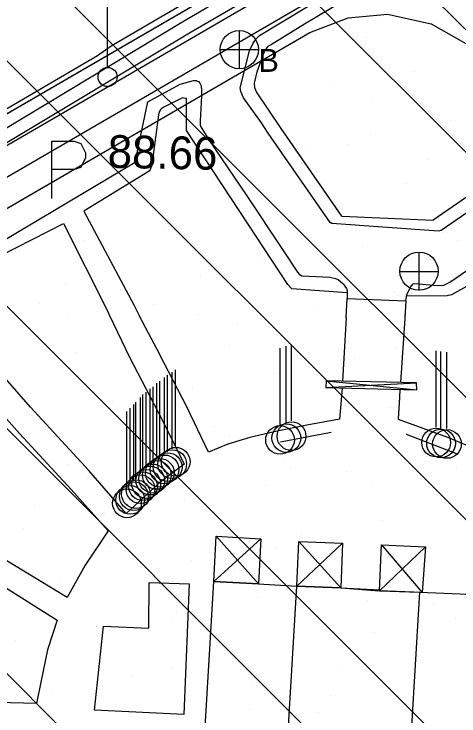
# Model space of a CAD drawing. Extents: x 417995 to 421451, y 4454518 to 4458015.
# Drawn here: x 420647.4 to 420728.9, y 4455736 to 4455864.6 of the extents above; entities that cross this region are included whole.
import ezdxf

# ---------------------------------------------------------------- set-up
doc = ezdxf.new("R2010")
doc.units = 0
for name, color, linetype in [('ADAKENARI', 7, 'Continuous'), ('B_Sundurma', 7, 'Continuous'), ('B_Teras', 7, 'Continuous'), ('B_Ticari', 7, 'Continuous'), ('KALDIRIM_FAT', 7, 'Continuous'), ('PL_AYA_FUAR', 7, 'Continuous'), ('PL_TA_K_OTOPARK', 7, 'Continuous'), ('S_Bayrak_Diregi', 7, 'Continuous'), ('S_Cad_Sok_Lambasi', 7, 'Continuous'), ('S_Otopark', 7, 'Continuous'), ('S_Rogar_Kapagi', 7, 'Continuous'), ('S_Rogar_Kapagi_Buski', 7, 'Continuous'), ('Sinir_Duvar_tek_tarafa_ait', 7, 'Continuous'), ('SN_TR_SIVILASMA', 7, 'Continuous'), ('TRFAT_PARKALANI', 7, 'Continuous'), ('Y_Kot_Noktasi', 7, 'Continuous'), ('Yol_Kaldirim_kenari_bordurtasi', 7, 'Continuous'), ('Yol_Sose', 7, 'Continuous')]:
    doc.layers.add(name, color=color, linetype=linetype)

msp = doc.modelspace()

# ---------------------------------------------------------------- linework, layer by layer
at = {"layer": 'ADAKENARI'}
for p, q in [((420604.42, 4455822.11), (420705.46, 4455880.83)), ((420701.58, 4455861.23), (420708.62, 4455863.92)), ((420708.62, 4455863.92), (420715.79, 4455864.57)), ((420715.79, 4455864.57), (420723.78, 4455862.78)), ((420723.78, 4455862.78), (420730.13, 4455859.19)), ((420636.29, 4455823.29), (420701.58, 4455861.23))]:
    msp.add_line(p, q, dxfattribs=at)
at = {"layer": 'B_Sundurma'}
for p, q in [((420704.5, 4455796.18), (420721.12, 4455797.04)), ((420704.55, 4455797.37), (420721.15, 4455795.75)), ((420684.45, 4455768.93), (420692.15, 4455760.19)), ((420684.01, 4455760.64), (420692.63, 4455768.41)), ((420699.18, 4455759.77), (420707.57, 4455767.63)), ((420707.23, 4455759.46), (420699.57, 4455767.97)), ((420714.33, 4455758.9), (420722.74, 4455766.97)), ((420714.69, 4455767.31), (420722.13, 4455758.62))]:
    msp.add_line(p, q, dxfattribs=at)
for points in [[(420704.55, 4455797.37), (420704.5, 4455796.18), (420721.15, 4455795.75), (420721.12, 4455797.04)], [(420684.01, 4455760.64), (420684.45, 4455768.93), (420692.63, 4455768.41), (420692.15, 4455760.19)], [(420707.23, 4455759.46), (420699.18, 4455759.77), (420699.57, 4455767.97), (420707.57, 4455767.63)], [(420714.33, 4455758.9), (420714.69, 4455767.31), (420722.74, 4455766.97), (420722.13, 4455758.62)]]:
    msp.add_lwpolyline(points, close=True, dxfattribs=at)
at = {"layer": 'B_Teras'}
msp.add_lwpolyline([(420707.23, 4455759.46), (420714.33, 4455759.07), (420714.33, 4455758.9), (420721.68, 4455758.64), (420713.06, 4455614.09), (420690.62, 4455615.29), (420699.18, 4455759.77)], close=True, dxfattribs=at)
at = {"layer": 'B_Ticari'}
msp.add_lwpolyline([(420697.3, 4455727.99), (420682.12, 4455728.78), (420684.01, 4455760.64), (420692.15, 4455760.19), (420699.18, 4455759.77), (420707.23, 4455759.46), (420714.33, 4455758.9), (420721.68, 4455758.64), (420729.13, 4455758.34), (420737.12, 4455757.88), (420735.52, 4455725.84), (420719.77, 4455726.58), (420713.06, 4455614.09), (420690.62, 4455615.29)], close=True, dxfattribs=at)
at = {"layer": 'KALDIRIM_FAT'}
for p, q in [((420608.38, 4455818.63), (420728.5, 4455888.44)), ((420612.88, 4455815.46), (420730.07, 4455883.57))]:
    msp.add_line(p, q, dxfattribs=at)
at = {"layer": 'PL_AYA_FUAR'}
msp.add_lwpolyline([(420545.42, 4455447.04), (420563.93, 4455742.84), (420564.49, 4455748.45), (420565.48, 4455754), (420566.88, 4455759.47), (420568.69, 4455764.8), (420570.9, 4455769.99), (420573.49, 4455775), (420576.46, 4455779.79), (420579.77, 4455784.35), (420583.42, 4455788.65), (420587.39, 4455792.66), (420591.64, 4455796.35), (420596.17, 4455799.72), (420600.93, 4455802.74), (420701.58, 4455861.23), (420708.62, 4455863.92), (420715.79, 4455864.57), (420723.78, 4455862.78), (420730.13, 4455859.19), (420735, 4455853.4), (420771.9, 4455797.51), (420787.06, 4455778.4), (420884.04, 4455668.02)], dxfattribs=at)
at = {"layer": 'PL_TA_K_OTOPARK'}
msp.add_lwpolyline([(420578.04, 4455894.75), (420621.81, 4455921.26), (420693.23, 4455965.73), (420713.63, 4455902.08), (420714.27, 4455899.43), (420714.5, 4455896.71), (420714.32, 4455893.98), (420713.73, 4455891.31), (420712.75, 4455888.76), (420711.4, 4455886.39), (420709.7, 4455884.25), (420707.71, 4455882.38), (420705.46, 4455880.83), (420604.42, 4455822.11), (420593.39, 4455815.7), (420591.4, 4455814.51), (420589.43, 4455813.26), (420587.5, 4455811.97), (420585.61, 4455810.62), (420583.75, 4455809.23), (420581.92, 4455807.78), (420580.13, 4455806.29), (420578.39, 4455804.76), (420550.56, 4455835.6)], close=True, dxfattribs=at)
at = {"layer": 'S_Bayrak_Diregi'}
for p, q in [((420696.12, 4455789.38), (420696.12, 4455803.38)), ((420697.26, 4455789.72), (420697.26, 4455803.72)), ((420698.23, 4455790.07), (420698.23, 4455804.07)), ((420724.69, 4455788.9), (420724.69, 4455802.9)), ((420725.59, 4455788.74), (420725.59, 4455802.74)), ((420726.68, 4455788.64), (420726.68, 4455802.64)), ((420675.53, 4455784.4), (420675.53, 4455798.4)), ((420676.37, 4455784.95), (420676.37, 4455798.95)), ((420677.01, 4455785.39), (420677.01, 4455799.39)), ((420673.56, 4455782.96), (420673.56, 4455796.96)), ((420674.09, 4455783.35), (420674.09, 4455797.35)), ((420674.97, 4455783.98), (420674.97, 4455797.98)), ((420672.36, 4455781.91), (420672.36, 4455795.91)), ((420672.88, 4455782.28), (420672.88, 4455796.28)), ((420671.02, 4455780.89), (420671.02, 4455794.89)), ((420671.62, 4455781.3), (420671.62, 4455795.3)), ((420669.33, 4455779.08), (420669.33, 4455793.08)), ((420669.72, 4455779.46), (420669.72, 4455793.46)), ((420670.56, 4455780.34), (420670.56, 4455794.34)), ((420668.66, 4455778.39), (420668.66, 4455792.39)), ((420668.08, 4455777.75), (420668.08, 4455791.75))]:
    msp.add_line(p, q, dxfattribs=at)
for centre in [(420697.27, 4455786.9), (420698.23, 4455787.25), (420696.12, 4455786.56), (420724.7, 4455786.08), (420725.6, 4455785.92), (420726.68, 4455785.82), (420675.54, 4455781.58), (420676.38, 4455782.13), (420677.02, 4455782.57), (420674.1, 4455780.53), (420674.97, 4455781.16), (420672.36, 4455779.1), (420672.88, 4455779.46), (420673.56, 4455780.14), (420671.03, 4455778.07), (420671.63, 4455778.48), (420669.73, 4455776.64), (420670.57, 4455777.52), (420668.67, 4455775.57), (420669.34, 4455776.26), (420668.09, 4455774.94)]:
    msp.add_circle(centre, 2.63, dxfattribs=at)
at = {"layer": 'S_Cad_Sok_Lambasi'}
msp.add_line((420664.55, 4455854.81), (420664.55, 4455869.48), dxfattribs=at)
msp.add_circle((420664.55, 4455853.06), 1.75, dxfattribs=at)
at = {"layer": 'S_Otopark'}
for points in [[(420654.33, 4455841.29), (420658.43, 4455841.29)], [(420654.33, 4455830.79), (420654.33, 4455841.29)], [(420658.43, 4455841.29), (420659.65, 4455840.87), (420660.49, 4455839.16), (420660.49, 4455838.25), (420659.65, 4455836.46), (420658.43, 4455836.11)], [(420658.43, 4455836.11), (420654.33, 4455836.11)]]:
    msp.add_lwpolyline(points, dxfattribs=at)
at = {"layer": 'S_Rogar_Kapagi'}
for p, q in [((420721.62, 4455813.95), (420721.62, 4455820.95)), ((420718.05, 4455817.41), (420725.05, 4455817.41))]:
    msp.add_line(p, q, dxfattribs=at)
msp.add_circle((420721.57, 4455817.48), 3.5, dxfattribs=at)
at = {"layer": 'S_Rogar_Kapagi_Buski'}
for p, q in [((420688.66, 4455861.57), (420688.66, 4455854.57)), ((420685.16, 4455858.07), (420692.16, 4455858.07))]:
    msp.add_line(p, q, dxfattribs=at)
msp.add_circle((420688.66, 4455858.07), 3.5, dxfattribs=at)
at = {"layer": 'Sinir_Duvar_tek_tarafa_ait'}
for points in [[(420696.19, 4455786.2), (420705.46, 4455788)], [(420719.19, 4455787.6), (420728.54, 4455784.04)]]:
    msp.add_lwpolyline(points, dxfattribs=at)
at = {"layer": 'SN_TR_SIVILASMA'}
for p, q in [((421269.77, 4455322.09), (420183.63, 4456408.23)), ((421269.54, 4455299.87), (420176.15, 4456393.26)), ((421269.08, 4455255.43), (420161.18, 4456363.33)), ((421268.85, 4455233.21), (420151.38, 4456350.68)), ((421268.38, 4455188.77), (420123.47, 4456333.68)), ((421268.15, 4455166.56), (420116.87, 4456317.84)), ((421267.69, 4455122.12), (420103.66, 4456286.14))]:
    msp.add_line(p, q, dxfattribs=at)
at = {"layer": 'TRFAT_PARKALANI'}
for p, q in [((420714.05, 4455863.09), (420714.05, 4455863.09)), ((420711.98, 4455860.33), (420711.98, 4455860.33)), ((420720.71, 4455854.11), (420720.71, 4455854.11)), ((420705.94, 4455851.51), (420705.94, 4455851.51)), ((420691.16, 4455848.9), (420691.16, 4455848.9)), ((420713.09, 4455849.38), (420713.09, 4455849.38)), ((420694.6, 4455848.16), (420694.6, 4455848.16)), ((420676.39, 4455846.3), (420676.39, 4455846.3)), ((420678.96, 4455845.84), (420678.96, 4455845.84)), ((420677.26, 4455845.42), (420677.26, 4455845.42)), ((420727.37, 4455845.13), (420727.37, 4455845.13)), ((420712.6, 4455842.53), (420712.6, 4455842.53)), ((420697.82, 4455839.92), (420697.82, 4455839.92)), ((420701.6, 4455839.74), (420701.6, 4455839.74)), ((420708.51, 4455840.63), (420708.51, 4455840.63)), ((420683.05, 4455837.32), (420683.05, 4455837.32)), ((420723.28, 4455838.03), (420723.28, 4455838.03)), ((420665.77, 4455835.78), (420665.77, 4455835.78)), ((420668.28, 4455834.71), (420668.28, 4455834.71)), ((420661.59, 4455833.68), (420661.59, 4455833.68)), ((420719.26, 4455833.55), (420719.26, 4455833.55)), ((420653.51, 4455832.11), (420653.51, 4455832.11)), ((420704.49, 4455830.94), (420704.49, 4455830.94)), ((420689.71, 4455828.34), (420689.71, 4455828.34)), ((420674.94, 4455825.73), (420674.94, 4455825.73)), ((420675.49, 4455826.15), (420675.49, 4455826.15)), ((420705.9, 4455825.86), (420705.9, 4455825.86)), ((420725.92, 4455824.57), (420725.92, 4455824.57)), ((420660.17, 4455823.13), (420660.17, 4455823.13)), ((420690.26, 4455823.54), (420690.26, 4455823.54)), ((420728.55, 4455823.18), (420728.55, 4455823.18)), ((420711.15, 4455821.96), (420711.15, 4455821.96)), ((420692.71, 4455819.22), (420692.71, 4455819.22)), ((420696.37, 4455819.36), (420696.37, 4455819.36)), ((420719.81, 4455818.33), (420719.81, 4455818.33)), ((420681.6, 4455816.75), (420681.6, 4455816.75)), ((420656.87, 4455815.26), (420656.87, 4455815.26)), ((420666.83, 4455814.15), (420666.83, 4455814.15)), ((420717.06, 4455813.54), (420717.06, 4455813.54)), ((420717.81, 4455812.98), (420717.81, 4455812.98)), ((420652.06, 4455811.54), (420652.06, 4455811.54)), ((420672.89, 4455811.38), (420672.89, 4455811.38)), ((420703.03, 4455810.38), (420703.03, 4455810.38)), ((420657.25, 4455809.06), (420657.25, 4455809.06)), ((420681.22, 4455809.58), (420681.22, 4455809.58)), ((420688.26, 4455807.77), (420688.26, 4455807.77)), ((420673.49, 4455805.17), (420673.49, 4455805.17)), ((420686.79, 4455803.85), (420686.79, 4455803.85)), ((420717.2, 4455803.56), (420717.2, 4455803.56)), ((420724.47, 4455804), (420724.47, 4455804)), ((420658.72, 4455802.56), (420658.72, 4455802.56)), ((420701.56, 4455801.24), (420701.56, 4455801.24)), ((420709.69, 4455801.4), (420709.69, 4455801.4)), ((420694.92, 4455798.79), (420694.92, 4455798.79)), ((420680.15, 4455796.19), (420680.15, 4455796.19)), ((420665.38, 4455793.58), (420665.38, 4455793.58)), ((420708.16, 4455793.03), (420708.16, 4455793.03)), ((420716.36, 4455792.42), (420716.36, 4455792.42)), ((420650.61, 4455790.98), (420650.61, 4455790.98)), ((420653.77, 4455789.36), (420653.77, 4455789.36)), ((420701.58, 4455789.81), (420701.58, 4455789.81)), ((420672.33, 4455789.06), (420672.33, 4455789.06)), ((420684.19, 4455789.08), (420684.19, 4455789.08)), ((420668.55, 4455786.76), (420668.55, 4455786.76)), ((420686.81, 4455787.21), (420686.81, 4455787.21)), ((420672.04, 4455784.6), (420672.04, 4455784.6)), ((420696.67, 4455783.39), (420696.67, 4455783.39)), ((420723.02, 4455783.44), (420723.02, 4455783.44)), ((420657.27, 4455782), (420657.27, 4455782)), ((420698.09, 4455781.55), (420698.09, 4455781.55)), ((420708.24, 4455780.83), (420708.24, 4455780.83)), ((420728.5, 4455781.26), (420728.5, 4455781.26)), ((420660.84, 4455779.42), (420660.84, 4455779.42)), ((420712.86, 4455778.94), (420712.86, 4455778.94)), ((420693.47, 4455778.23), (420693.47, 4455778.23)), ((420678.7, 4455775.62), (420678.7, 4455775.62)), ((420651.17, 4455774.59), (420651.17, 4455774.59)), ((420663.93, 4455773.02), (420663.93, 4455773.02)), ((420714.9, 4455771.85), (420714.9, 4455771.85)), ((420649.15, 4455770.41), (420649.15, 4455770.41)), ((420700.13, 4455769.25), (420700.13, 4455769.25)), ((420665.07, 4455767.06), (420665.07, 4455767.06)), ((420685.36, 4455766.64), (420685.36, 4455766.64)), ((420695.49, 4455766.77), (420695.49, 4455766.77)), ((420723.62, 4455766.83), (420723.62, 4455766.83)), ((420670.59, 4455764.04), (420670.59, 4455764.04)), ((420679.84, 4455764.45), (420679.84, 4455764.45)), ((420687.78, 4455762.87), (420687.78, 4455762.87)), ((420721.56, 4455762.87), (420721.56, 4455762.87)), ((420655.82, 4455761.43), (420655.82, 4455761.43)), ((420706.79, 4455760.27), (420706.79, 4455760.27)), ((420651.94, 4455758.91), (420651.94, 4455758.91)), ((420709.39, 4455759.25), (420709.39, 4455759.25)), ((420692.02, 4455757.66), (420692.02, 4455757.66)), ((420712.13, 4455757.19), (420712.13, 4455757.19)), ((420724.16, 4455756.64), (420724.16, 4455756.64)), ((420677.25, 4455755.06), (420677.25, 4455755.06)), ((420676.29, 4455753.23), (420676.29, 4455753.23)), ((420728.22, 4455753.89), (420728.22, 4455753.89)), ((420662.47, 4455752.29), (420662.47, 4455752.29)), ((420662.48, 4455752.45), (420662.48, 4455752.45)), ((420713.45, 4455751.29), (420713.45, 4455751.29)), ((420647.7, 4455749.85), (420647.7, 4455749.85)), ((420698.68, 4455748.68), (420698.68, 4455748.68)), ((420683.91, 4455746.08), (420683.91, 4455746.08)), ((420676.37, 4455744.76), (420676.37, 4455744.76)), ((420706.78, 4455744.47), (420706.78, 4455744.47)), ((420669.14, 4455743.47), (420669.14, 4455743.47)), ((420691.14, 4455742.15), (420691.14, 4455742.15)), ((420720.11, 4455742.31), (420720.11, 4455742.31)), ((420654.36, 4455740.87), (420654.36, 4455740.87)), ((420705.34, 4455739.7), (420705.34, 4455739.7)), ((420690.57, 4455737.1), (420690.57, 4455737.1)), ((420703.23, 4455736.67), (420703.23, 4455736.67)), ((420720.69, 4455736.94), (420720.69, 4455736.94))]:
    msp.add_line(p, q, dxfattribs=at)
at = {"layer": 'Yol_Kaldirim_kenari_bordurtasi'}
for points in [[(420696.32, 4455843.59), (420691.79, 4455850.34), (420691.51, 4455851.08), (420691.46, 4455851.94), (420691.48, 4455852.2), (420691.96, 4455854.02), (420693.25, 4455857.72), (420693.92, 4455858.68), (420694.38, 4455858.98), (420700.61, 4455862.81), (420719.25, 4455873.99), (420719.51, 4455874.11), (420720.61, 4455874.44), (420722.12, 4455874.47), (420723.26, 4455874.39), (420724.47, 4455874.13), (420725.59, 4455873.78), (420726.65, 4455873.3), (420727.3, 4455872.88), (420728, 4455872.21), (420728.63, 4455871.32), (420742.38, 4455850)], [(420641.01, 4455840.76), (420677.83, 4455862.92), (420691.88, 4455871.22)], [(420708.4, 4455813.54), (420698.29, 4455814.24), (420697.54, 4455815.05), (420690.31, 4455826.1), (420679.01, 4455843.25), (420679.01, 4455849.11), (420678.8, 4455849.13), (420678.29, 4455849.25), (420674.86, 4455847.5), (420674.32, 4455847.14), (420673.99, 4455846.67), (420673.88, 4455846.11), (420672.64, 4455836.92), (420672.35, 4455836.13), (420672.16, 4455835.83), (420660.2, 4455828.5), (420669.33, 4455811.34), (420670.32, 4455809.38)], [(420707.45, 4455827.53), (420696.32, 4455843.59)], [(420730.45, 4455831.18), (420724.13, 4455826.83)], [(420766.54, 4455812.55), (420755.56, 4455829.33), (420755.09, 4455829.74), (420754.69, 4455829.78), (420754.07, 4455829.6), (420744.74, 4455823.26), (420730.78, 4455814.98), (420727.5, 4455813.12), (420726.72, 4455812.98), (420719.28, 4455812.88)], [(420707.45, 4455827.53), (420724.13, 4455826.83)], [(420635.05, 4455809.78), (420627.28, 4455818.75), (420635.3, 4455823.1), (420645.03, 4455820.32), (420656.5, 4455826.2), (420664.45, 4455810.33)], [(420708.22, 4455808.98), (420708.43, 4455812.47)], [(420719.17, 4455812.05), (420718.95, 4455808.87)], [(420664.45, 4455810.33), (420664.9, 4455809.37)], [(420719.05, 4455810.23), (420718.95, 4455808.81)], [(420664.9, 4455809.37), (420668.53, 4455801.74)], [(420670.32, 4455809.38), (420670.35, 4455809.32)], [(420670.35, 4455809.32), (420674.1, 4455802.14)], [(420708.21, 4455808.92), (420707.54, 4455797.31)], [(420708.22, 4455808.98), (420708.21, 4455808.92)], [(420708.21, 4455808.92), (420708.22, 4455808.98)], [(420718.95, 4455808.81), (420718.16, 4455797.1)], [(420718.95, 4455808.87), (420718.95, 4455808.81)], [(420634.12, 4455803.8), (420641.62, 4455795.3), (420648.41, 4455787.74), (420657.85, 4455777.5), (420664.68, 4455769.91), (420660.46, 4455763.61), (420657.12, 4455757.68), (420646.08, 4455764.38), (420631.12, 4455774.41), (420619.24, 4455782.13), (420609.97, 4455788.64), (420596.53, 4455797.53), (420605.99, 4455805.15)], [(420718.08, 4455795.83), (420717.98, 4455794.34), (420717.73, 4455790.34), (420726.75, 4455787.07), (420736.43, 4455783.06), (420743.66, 4455780.11), (420749.34, 4455788.21), (420756.99, 4455798.95), (420761.35, 4455805.16)], [(420668.53, 4455801.74), (420674.58, 4455790.12), (420678.54, 4455782.11), (420674.16, 4455778.83), (420667.93, 4455773.06), (420661.11, 4455780.96), (420650.45, 4455792.57), (420640.44, 4455803.97)], [(420707.47, 4455796.1), (420707.38, 4455794.58), (420707.02, 4455790.34), (420701.04, 4455789.29), (420695.58, 4455788.19), (420690.6, 4455787.02), (420686.56, 4455785.79), (420683.05, 4455784.3), (420679.06, 4455792.65), (420674.02, 4455802.29)], [(420575.04, 4455735.47), (420565.68, 4455736.02), (420567.19, 4455745.02), (420568.7, 4455751.51), (420570.38, 4455756.73), (420572.94, 4455763.44), (420575.68, 4455770.16), (420577.97, 4455774.55), (420580.92, 4455779.55), (420583.86, 4455783.48), (420588.27, 4455788.45), (420592.97, 4455794.07), (420602.45, 4455787.64), (420614.94, 4455779.42), (420626.8, 4455771.83), (420639.34, 4455763.61), (420655.33, 4455753.52), (420653.57, 4455748.07), (420652.34, 4455742.15), (420651.56, 4455738.28), (420639.55, 4455738.58), (420618.39, 4455740.03), (420611.03, 4455740.52), (420610.52, 4455733.57)], [(420662.16, 4455737.03), (420663.79, 4455752.41), (420672.09, 4455752.04), (420672.17, 4455760.46), (420679.5, 4455760.22), (420678.48, 4455736.28)], [(420678.48, 4455736.28), (420662.16, 4455737.03)]]:
    msp.add_lwpolyline(points, dxfattribs=at)
at = {"layer": 'Yol_Sose'}
for points in [[(420692.73, 4455844.68), (420689.45, 4455849.22), (420688.92, 4455850.38), (420688.85, 4455851.07), (420690.54, 4455857.84), (420691.2, 4455859.26), (420691.73, 4455860.04), (420692.38, 4455860.63), (420696.23, 4455862.96), (420717.99, 4455876.15), (420719.21, 4455876.69), (420720.87, 4455876.75), (420722.95, 4455876.67), (420724.79, 4455876.35), (420727, 4455875.54), (420728.77, 4455874.7), (420729.9, 4455873.83)], [(420640.57, 4455844.05), (420662.71, 4455856.98), (420665.23, 4455858.74), (420690.7, 4455873.74)], [(420691.94, 4455870.66), (420691.82, 4455869.63), (420691.69, 4455868.83), (420691.33, 4455868.05), (420690.91, 4455867.74), (420679.87, 4455861.28), (420644.2, 4455839.91), (420643.68, 4455839.89), (420641.3, 4455840.59), (420639.67, 4455841.52)], [(420671.93, 4455848.48), (420677.81, 4455851.72), (420680.29, 4455852.4), (420680.74, 4455852.4), (420680.85, 4455852.38), (420681.19, 4455852.21), (420681.46, 4455851.92), (420681.68, 4455851.46), (420681.75, 4455850.55), (420681.71, 4455849.56)], [(420634.71, 4455825.71), (420644.82, 4455822.73), (420669.58, 4455837.48), (420671.93, 4455848.48)], [(420681.71, 4455849.56), (420681.55, 4455846.13), (420681.49, 4455844.99), (420681.49, 4455844.29), (420681.61, 4455843.94), (420683.1, 4455841.54), (420690.06, 4455831.26), (420696.6, 4455821.47), (420699.29, 4455817.3), (420699.62, 4455816.95), (420700.12, 4455816.63), (420705.24, 4455816.36), (420706.3, 4455816.15), (420706.79, 4455815.96), (420707.7, 4455815.15), (420708.27, 4455814.31), (420708.39, 4455813.89), (420708.43, 4455812.47), (420719.17, 4455812.05), (420719.32, 4455813.14), (420720.02, 4455814.54), (420720.47, 4455815.13), (420720.79, 4455815.2), (420724.98, 4455814.88), (420726.08, 4455814.93), (420726.33, 4455815.03), (420727.22, 4455815.48), (420732.62, 4455819.22)], [(420738.91, 4455834.09), (420725.6, 4455824.93), (420725.14, 4455824.78), (420705.59, 4455826.21), (420705.27, 4455826.37), (420693.97, 4455842.75), (420692.73, 4455844.68)]]:
    msp.add_lwpolyline(points, dxfattribs=at)

# ---------------------------------------------------------------- texts
at = {"layer": 'S_Rogar_Kapagi_Buski'}
msp.add_text('B', height=4.2, dxfattribs=at).set_placement((420692.16, 4455854))
at = {"layer": 'Y_Kot_Noktasi'}
msp.add_text('88.66', height=6, rotation=358.8289, dxfattribs=at).set_placement((420664.52, 4455836.44))

doc.saveas('drawing.dxf')
